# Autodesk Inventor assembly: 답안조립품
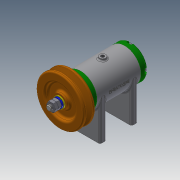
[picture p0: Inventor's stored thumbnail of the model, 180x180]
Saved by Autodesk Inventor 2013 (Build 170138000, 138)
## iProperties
Created: 2020-07
Part Number: 답안조립품
Document SubType Name: Weldment
Designer: user
Weld Material: Welded Aluminum-6061
Author: user
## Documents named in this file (15)
- C:\Users\user\Desktop\700706V1037\답안조립품.iam
- C:\Users\user\Desktop\700706V1037\V벨트풀리.ipt
- C:\Users\user\Desktop\700706V1037\너트 M8.ipt
- C:\Users\user\Desktop\700706V1037\뒤커버.ipt
- C:\Users\user\Desktop\700706V1037\베어링 6002.ipt
- C:\Users\user\Desktop\700706V1037\본체.ipt
- C:\Users\user\Desktop\700706V1037\볼트 M4x12.ipt
- C:\Users\user\Desktop\700706V1037\볼트 M6x8.ipt
- C:\Users\user\Desktop\700706V1037\스프링와셔 8.ipt
- C:\Users\user\Desktop\700706V1037\앞커버.ipt
- C:\Users\user\Desktop\700706V1037\오일 실 15 25 7.ipt
- C:\Users\user\Desktop\700706V1037\와셔 6x11.5.ipt
- C:\Users\user\Desktop\700706V1037\와셔 8x17.ipt
- C:\Users\user\Desktop\700706V1037\축.ipt
- C:\Users\user\Desktop\700706V1037\키 3x3x12.ipt
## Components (1 placed, 1 different names)
1. V벨트풀리:1
